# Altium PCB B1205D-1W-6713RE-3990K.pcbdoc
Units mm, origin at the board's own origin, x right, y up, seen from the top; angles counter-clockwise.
Board outline 33 x 16 mm, 2 copper layers (Top Layer, Bottom Layer), stack 0.78 mm thick; 14 components, 9 nets, 36 pads, 14 vias.
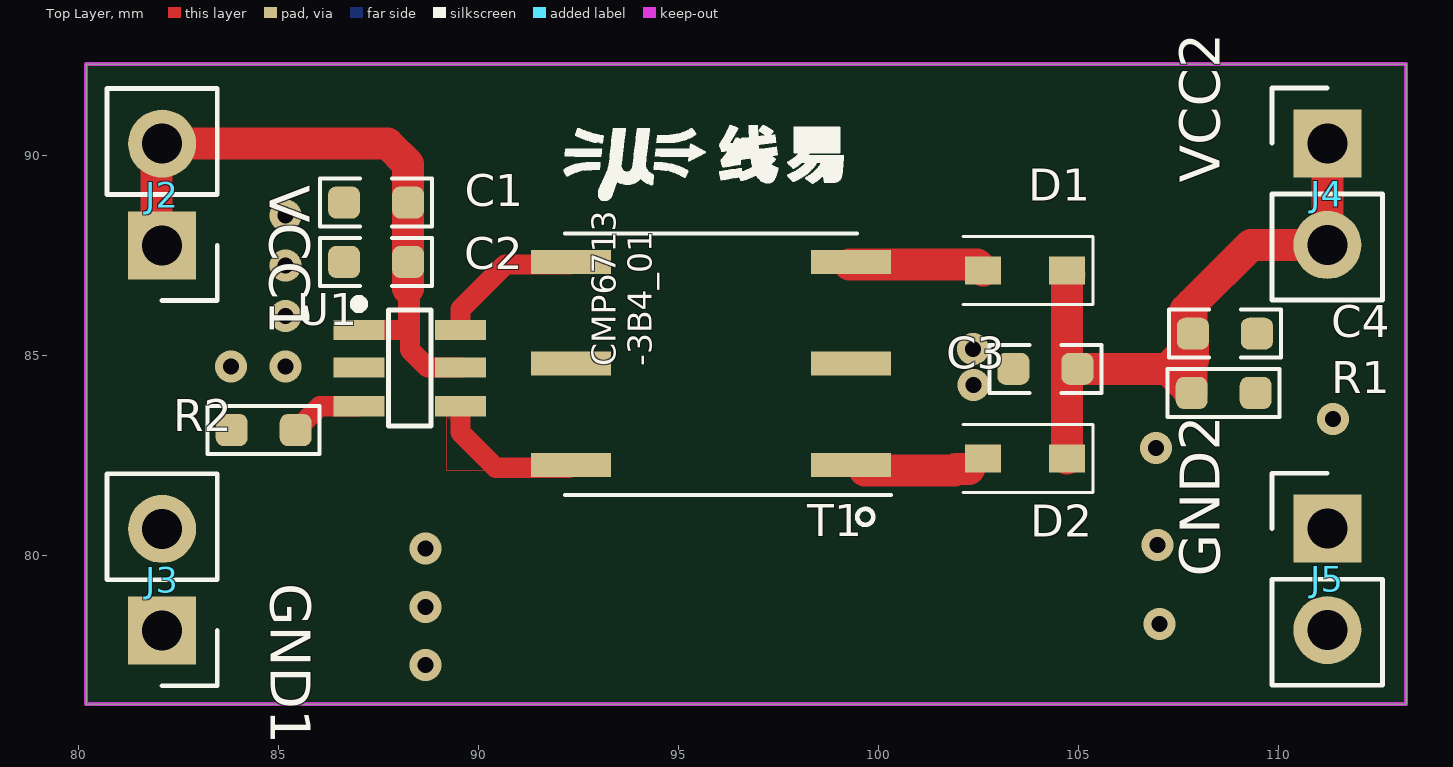
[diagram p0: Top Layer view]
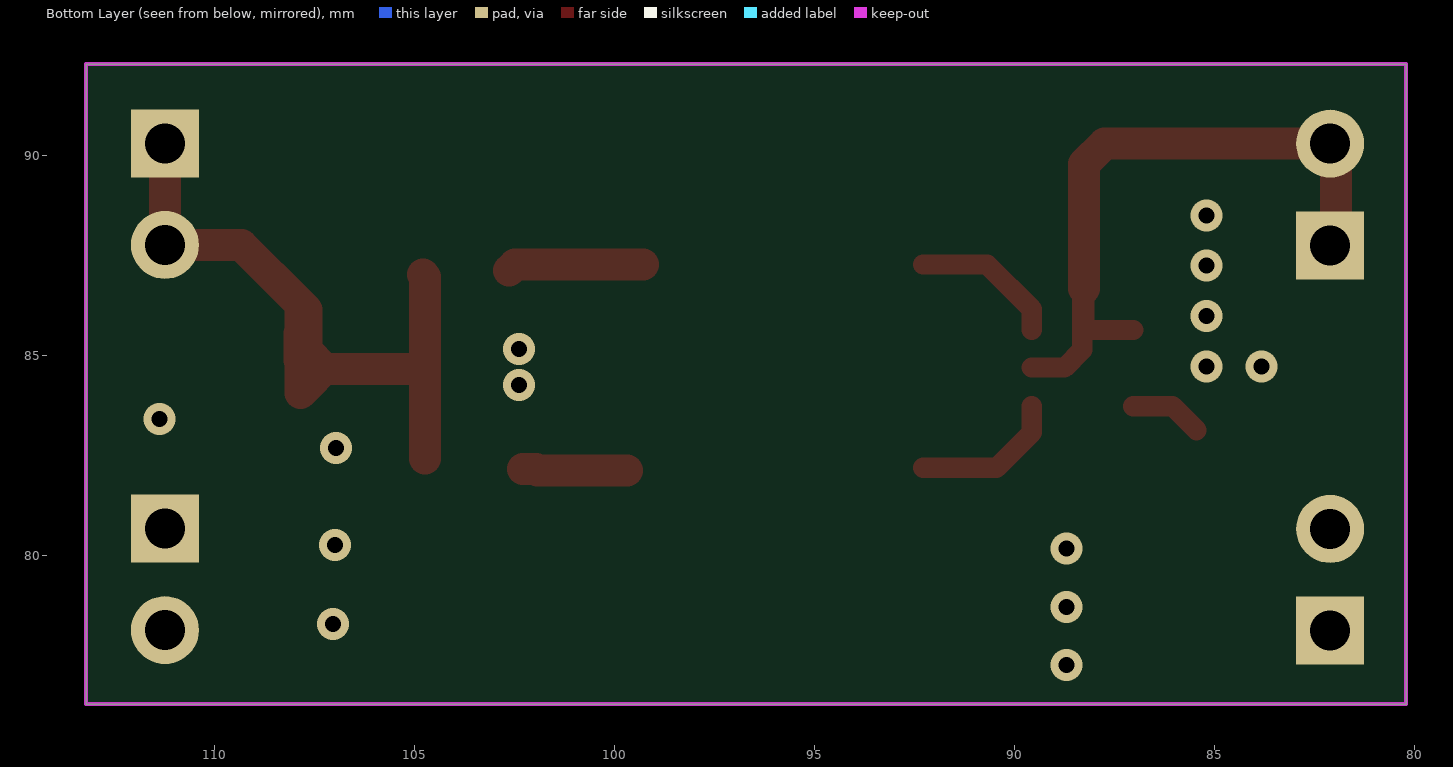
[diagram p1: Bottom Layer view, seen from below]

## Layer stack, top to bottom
Top Solder Mask Layer: solder mask 0.01, Dk 0
Top Layer: signal copper 0.035
dielectric 1: surface 0.71, FR4, Dk 4.5
Bottom Layer: signal copper 0.035
Bottom Solder Mask Layer: solder mask 0.01, Dk 0

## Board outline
80.2,92.284 113.2,92.284 113.2,76.284 80.2,76.284

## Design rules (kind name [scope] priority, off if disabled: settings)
BoardOutlineClearance default [All] p0: genericclearance=0.254 ignorepadtopadclearanceinfootprint=FALSE except(0: Arc-SplitContinuation Track-SplitContinuation SMDPad-SplitContinuation THPad-SplitContinuation Via-SplitContinuation Fill-SplitContinuation Poly-SplitContinuation Region-SplitContinuation Text-SplitContinuation)
BoardOutlineClearance safeClearance [All] p0: genericclearance=0.254 ignorepadtopadclearanceinfootprint=FALSE except(0: Arc-SplitContinuation Track-SplitContinuation SMDPad-SplitContinuation THPad-SplitContinuation Via-SplitContinuation Fill-SplitContinuation Poly-SplitContinuation Region-SplitContinuation Text-SplitContinuation)
BoardOutlineClearance otherClearance [All] p0: genericclearance=0.254 ignorepadtopadclearanceinfootprint=FALSE except(0: Arc-SplitContinuation Track-SplitContinuation SMDPad-SplitContinuation THPad-SplitContinuation Via-SplitContinuation Fill-SplitContinuation Poly-SplitContinuation Region-SplitContinuation Text-SplitContinuation)
Clearance default [All] p1: gap=0.178 ignorepadtopadclearanceinfootprint=FALSE
Clearance safeClearance [All] p1: gap=0.178 ignorepadtopadclearanceinfootprint=FALSE
Clearance otherClearance [All] p1: gap=0.178 ignorepadtopadclearanceinfootprint=FALSE
DiffPairsRouting differentialPair [All] p1: maxuncoupledlength=10 minlimit=5 maxlimit=Infinity mostfreqgap=6 toplayer_minwidth=5 toplayer_prefwidth=100 toplayer_maxwidth=100 bottomlayer_minwidth=5 bottomlayer_prefwidth=100 bottomlayer_maxwidth=100
PasteMaskExpansion pasteMaskExpansion [All] p1: expansion=0
PlaneConnect innerPlane [All] p1: planeconnectstyle=Relief reliefexpansion=0.508 reliefentries=4 reliefconductorwidth=0.254 reliefairgap=0.254
PolygonConnect copper0 [All] p1: connectstyle=Direct reliefentries=4 reliefconductorwidth=10 polygonreliefangle="90 Angle" airgapwidth=10
PolygonConnect copper1 [All] p1: connectstyle=Direct reliefentries=4 reliefconductorwidth=10 polygonreliefangle="90 Angle" airgapwidth=10
PolygonConnect copper2 [All] p1: connectstyle=Direct reliefentries=4 reliefconductorwidth=10 polygonreliefangle="90 Angle" airgapwidth=10
RoutingVias viaSize [All] p1: viastyle="Through Hole" holewidth=24 minholewidth=11.811 maxholewidth=393.7 width=24 minwidth=11.811 maxwidth=393.7
SolderMaskExpansion solderMaskExpansion [All] p1: useseparateexpansions=TRUE expansion=2 expansionbottom=2
Width copperThickness1oz [All] p1: maxlimit=100 minlimit=5 preferedwidth=10

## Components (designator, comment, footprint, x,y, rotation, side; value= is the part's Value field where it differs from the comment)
C1 "10uF" C0603 87.45,88.824 r0 top
C2 "100nF" C0603 87.45,87.338 r0 top
C3 "10uF" C0603 104.18,84.668 r0 top
C4 "100nF" C0603 108.67,85.544 r180 top
D1 "B5819WS" SOD-323_L1.8-W1.3-LS2.5-RD 103.674,87.124 r180 top
D2 "B5819WS" SOD-323_L1.8-W1.3-LS2.5-RD 103.674,82.424 r180 top
J2 "HX PZ2.54-1x2P ZZ" HDR-TH_2P-P2.54-V-M-3 82.1,87.754 r180 top
J3 "HX PZ2.54-1x2P ZZ" HDR-TH_2P-P2.54-V-M-3 82.1,78.124 r180 top
J4 "HX PZ2.54-1x2P ZZ" HDR-TH_2P-P2.54-V-M-3 111.23,90.304 r0 top
J5 "HX PZ2.54-1x2P ZZ" HDR-TH_2P-P2.54-V-M-3 111.23,80.674 r0 top
R1 "4.7kΩ" R0603 108.64,84.064 r0 top
R2 "15kΩ" R0603 84.64,83.134 r180 top
T1 "" ? 95.692,84.669 r180 top
U1 "CMP6713RE" SOT-23-6_L2.9-W1.6-P0.95-LS2.8-BL-2 88.29,84.698 r0 top

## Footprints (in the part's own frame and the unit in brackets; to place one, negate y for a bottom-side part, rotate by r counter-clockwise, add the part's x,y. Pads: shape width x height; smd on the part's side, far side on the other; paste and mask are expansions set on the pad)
C0603 [mm]
  rrect50% 0.8x0.8 smd: 1(-0.8,0) 2(0.8,0)
  silkscreen extent -1.4,-0.6 1.4,0.6
HDR-TH_2P-P2.54-V-M-3 [mm]
  rect 1.7x1.7 hole 1: 1(0,0)
  round 1.7 hole 1: 2(0,-2.54)
  silkscreen extent -1.38,-3.92 1.38,1.38
R0603 [mm]
  rrect50% 0.8x0.8 smd: 1(-0.8,0) 2(0.8,0)
  silkscreen extent -1.4,-0.6 1.4,0.6
SOD-323_L1.8-W1.3-LS2.5-RD [mm]
  rect 0.9x0.7 smd: 1(-1.05,0) 2(1.05,0)
  silkscreen extent -1.7,-0.85 1.55,0.85
SOT-23-6_L2.9-W1.6-P0.95-LS2.8-BL-2 [mil]
  rect 50x20 smd: 1(-50,37) 2(-50,0) 3(-50,-38) 4(50,-38) 5(50,0) 6(50,37)
  silkscreen extent -54,-58 21,66
? [mm]
  rect 2x0.6 smd: 1(-3.627,2.413) 2(-3.627,-0.127) 3(-3.627,-2.667) 4(3.373,-2.667) 5(3.373,-0.127) 6(3.373,2.413)
  silkscreen extent -4.63,-3.38 3.52,3.9

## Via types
v1: diameter 0.8, hole 0.4, Top Layer to Bottom Layer, 14 vias

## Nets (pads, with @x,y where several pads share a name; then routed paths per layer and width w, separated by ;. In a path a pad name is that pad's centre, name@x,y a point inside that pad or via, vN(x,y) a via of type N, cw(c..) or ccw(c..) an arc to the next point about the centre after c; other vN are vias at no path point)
$1N5: D2.2 T1.1 | length 2.6
  Top Layer w0.8: T1.1@99.672,82.124 101.91,82.124 101.95,82.164 D2.2@102.274,82.164
$1N6: R2.1 U1.3 | length 1.8
  Top Layer w0.508: R2.1 86.039,83.732 U1.3
$1N7: D1.2 T1.3 | length 3.4
  Top Layer w0.8: T1.3@99.28,87.274 102.474,87.274 D1.2
$1N15: T1.4 U1.6 | length 3.7
  Top Layer w0.508: U1.6 89.56,86.162 90.672,87.274 T1.4@92.28,87.274
$1N16: T1.6 U1.4 | length 3.7
  Top Layer w0.508: U1.4 89.56,83.074 90.44,82.194 T1.6@92.28,82.194
GND1: C1.1 C2.1 J3.1 J3.2 R2.2 U1.2
  other v1: 88.69,77.259 88.69,78.716 88.69,80.174 83.82,84.724 85.19,84.724 85.19,85.984 85.19,87.244 85.19,88.504
GND2: C3.1 C4.1 J5.1 J5.2 R1.2 T1.2
  other v1: 107.03,78.284 106.98,80.264 106.95,82.684 111.37,83.414 102.383,84.264 102.374,85.164
VCC1: C1.2 C2.2 J2.1 J2.2 U1.1 U1.5 | length 17.1
  Top Layer w0.508: U1.1 88.19,85.637 88.25,85.698 88.25,86.674 88.296,86.628 88.296,85.142 88.74,84.698 U1.5
  Top Layer w0.8: J2.1@81.955,87.984 81.955,90.149 J2.2 87.74,90.294 88.25,89.784 C1.2 C2.2 88.25,86.674
VCC2: C3.2 C4.2 D1.1 D2.1 J4.1 J4.2 R1.1 | length 20
  Top Layer w0.8: D2.1 104.724,86.968 D1.1@104.78,87.024 ; C3.2 107.236,84.668 ; C4.2 107.87,84.884 107.84,84.854 ; J4.1 J4.2 109.32,87.764 107.84,86.284 ; 107.236,84.668 107.69,85.122 ; 107.236,84.668 R1.1@107.69,84.214 ; R1.1@107.69,84.214 R1.1 107.84,84.854 ; R1.1@107.69,84.214 107.69,85.122 ; 107.69,85.122 107.69,86.134 107.84,86.284 ; 107.84,84.854 107.84,86.284
pads on no net: T1.5

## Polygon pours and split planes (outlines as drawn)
GND1 on Top Layer (solid, remove dead copper, pour order 2): 86.995,89.129 86.995,82.129 89.2,82.129 89.2,76.304 76.32,76.304 76.32,84.104 78.62,84.104 80.72,86.204 80.72,89.129
GND1 on Top Layer (solid, remove dead copper, pour order 2): 89.2,82.129 90.74,82.129 89.2,83.495
GND1 on Bottom Layer (solid, remove dead copper, pour order 12): 91.9,76.284 76.2,76.284 76.2,92.284 91.9,92.284
GND2 on Top Layer (solid, remove dead copper, pour order 6): 103.888,83.768 102.024,83.768 102.024,83.764 101.738,84.068 98.314,84.068 98.264,85.268 101.688,85.268 101.924,85.664 101.924,85.668 103.888,85.668
GND2 on Top Layer (solid, remove dead copper, pour order 8): 113.324,76.2 106.27,76.25 106.3,76.254 106.279,79.934 106.279,83.33 108.754,83.33 108.954,83.63 108.954,86.16 113.324,86.16
GND2 on Bottom Layer (solid, remove dead copper, pour order 18): 113.225,76.299 96.975,76.351 96.975,92.351 113.225,92.299

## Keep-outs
Board Outline Layer:
  the board outline again, w0.1

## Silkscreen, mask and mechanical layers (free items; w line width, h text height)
Top Silkscreen Layer:
  drawing of 9 lines, arcs and shapes, not listed
  text "VCC2" at 108.54,89.324 h1 r90
  text "VCC1" at 84.79,89.254 h1 r270
  text "CMP6713 / -3B4_01" at 94.34,84.734 h0.6 r90
  text "GND2" at 108.54,79.464 h1 r90
  text "GND1" at 84.81,79.304 h1 r270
